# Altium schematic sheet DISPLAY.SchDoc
size A4; SheetNumber: 11; SheetTotal: 16
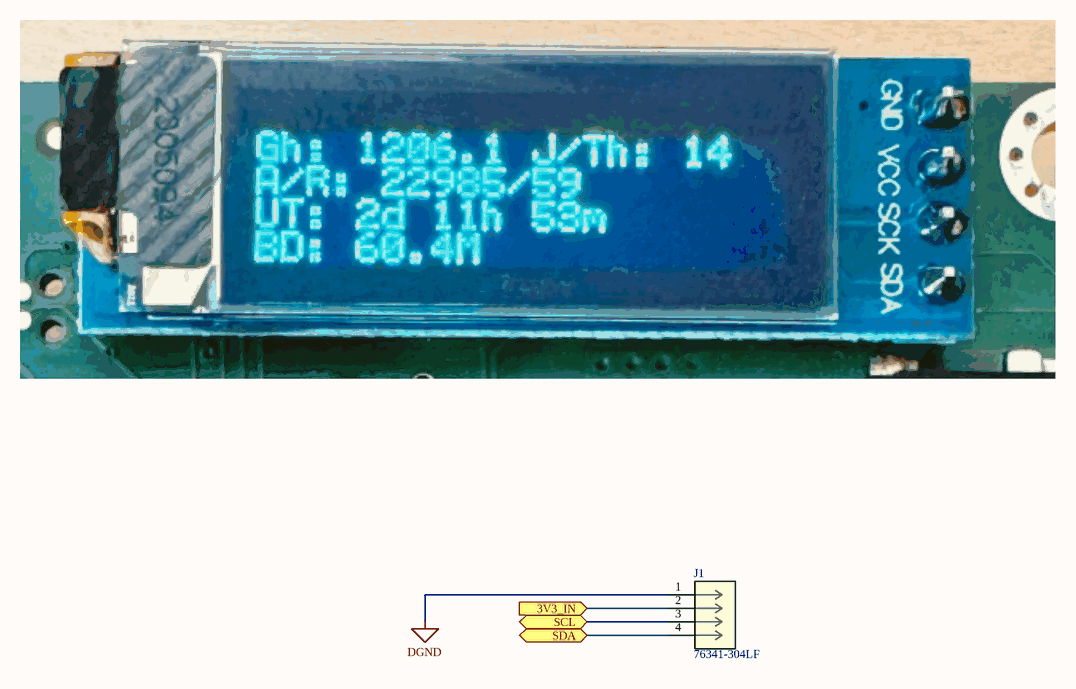
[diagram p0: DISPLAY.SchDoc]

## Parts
J1  76341-304LF  [76341-304LF-Footprint-1]

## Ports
3V3_IN (in), SCL (bidir), SDA (bidir)

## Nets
DGND: J1.1
3V3_IN: J1.2 ; port 3V3_IN
SCL: J1.3 ; port SCL
SDA: J1.4 ; port SDA

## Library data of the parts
J1 = CMP-x00140-1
